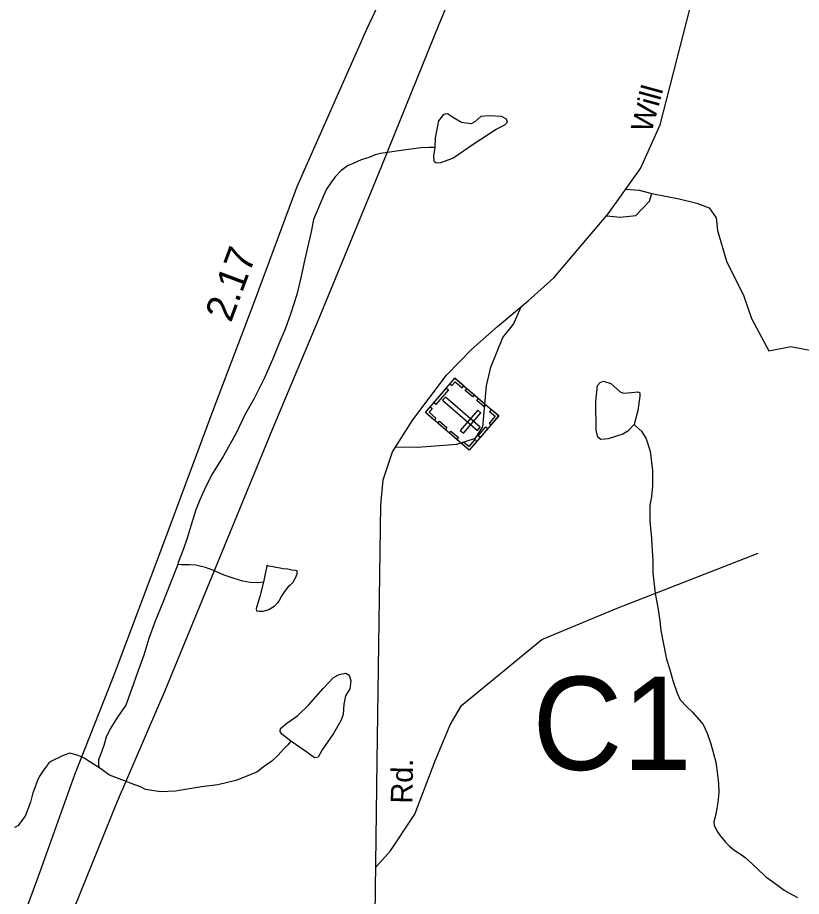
# Model space of a CAD drawing. Extents: x 2056842 to 2160602, y 826753 to 1016856.
# Drawn here: x 2070045 to 2073493, y 851288 to 855154 of the extents above; entities that cross this region are included whole.
import ezdxf

# ---------------------------------------------------------------- set-up
doc = ezdxf.new("R2010")
doc.units = 0
for name, color, linetype in [('Exist Cultural Cemetery CELL', 7, 'Continuous'), ('Exist Hydrographic Creek Single Shore', 7, 'Continuous'), ('Exist Hydrographic Misc Water Feature', 7, 'Continuous'), ('Exist Road Non-System Type 51', 7, 'Continuous'), ('Exist Road Primary Interstate Divided Center Attributed', 7, 'Continuous'), ('Exist Road Primary Interstate Mileage Hundredths English Label', 7, 'Continuous'), ('Exist Road Secondary Structure Culvert Number Label', 7, 'Continuous'), ('Exist Road Secondary Type 51 Attributed', 7, 'Continuous'), ('Exist Road Secondary Type 51 Label', 7, 'Continuous')]:
    doc.layers.add(name, color=color, linetype=linetype)

msp = doc.modelspace()

# ---------------------------------------------------------------- linework, layer by layer
at = {"layer": 'Exist Cultural Cemetery CELL'}
for points in [[(2072161.6, 853402), (2072031.9, 853251), (2071838.8, 853416.9), (2071968.5, 853567.9)], [(2071947, 853542.8), (2071955.7, 853535.3), (2071970, 853552), (2072000.7, 853525.7), (2072007.9, 853534.1), (2071968.6, 853568)], [(2071939.8, 853516.9), (2071884.5, 853452.5), (2071875.8, 853459.9), (2071931.1, 853524.3)], [(2072021.6, 853522.4), (2072054.4, 853494.2), (2072047, 853485.5), (2072014.2, 853513.8)], [(2072068.4, 853338.4), (2072080.5, 853352.6), (2071926.7, 853484.7), (2071914.5, 853470.6)], [(2072072.5, 853478.6), (2072105.4, 853450.3), (2072098, 853441.7), (2072065.1, 853469.9)], [(2071860.3, 853442.1), (2071869.1, 853434.6), (2071854.7, 853417.9), (2071885.4, 853391.6), (2071878.1, 853383.1), (2071838.8, 853416.9)], [(2072083.4, 853415.4), (2072069.2, 853427.6), (2071992.5, 853338.3), (2072006.7, 853326.1)], [(2072128.8, 853430.2), (2072121.4, 853421.6), (2072145.8, 853400.6), (2072119.4, 853369.9), (2072127.8, 853362.6), (2072161.6, 853402)], [(2071901, 853378.5), (2071933.8, 853350.2), (2071926.4, 853341.6), (2071893.6, 853369.8)], [(2072113.3, 853345.8), (2072079.6, 853306.5), (2072070.9, 853313.9), (2072104.7, 853353.3)], [(2071951, 853335.5), (2071983.8, 853307.3), (2071976.4, 853298.6), (2071943.5, 853326.8)], [(2071998.9, 853279.2), (2072006.3, 853287.8), (2072030.8, 853266.8), (2072057.2, 853297.6), (2072065.6, 853290.3), (2072031.8, 853251)]]:
    msp.add_lwpolyline(points, close=True, dxfattribs=at)
at = {"layer": 'Exist Hydrographic Creek Single Shore'}
for points in [[(2072757.3, 853363.7), (2072764.3, 853356.2), (2072789.3, 853334.2), (2072809.8, 853300.9), (2072827.7, 853247.2), (2072837.9, 853161.4), (2072837.9, 853094.9), (2072832.8, 853047.5), (2072826.4, 853008.3), (2072826.6, 852968.5), (2072826.6, 852940.5), (2072829.1, 852908.6), (2072832.8, 852862.5), (2072836.9, 852808.3), (2072838.9, 852766.7), (2072839.1, 852734.6), (2072839.3, 852710.6), (2072845.5, 852660.5), (2072849.4, 852620.6), (2072861.7, 852558.7), (2072869.9, 852500.7), (2072874, 852458.7), (2072887.5, 852390.4), (2072900, 852332.6), (2072912.1, 852290.5), (2072928.1, 852238.6), (2072946.1, 852182.7), (2072960.1, 852152.6), (2072988.4, 852122.8), (2073014.6, 852098.9), (2073042.5, 852065.1), (2073060.4, 852044.9), (2073078.6, 852006.8), (2073094.4, 851959), (2073106.7, 851917), (2073117, 851878.9), (2073124.5, 851823), (2073128.9, 851785), (2073129.1, 851745.2), (2073125.2, 851701.2), (2073121.1, 851675), (2073113.5, 851639.2), (2073107.3, 851617), (2073109.4, 851601.3), (2073121.5, 851577.2), (2073133.4, 851559.1), (2073159.4, 851527.2), (2073175.4, 851511.3), (2073197.1, 851491.4), (2073223.4, 851475.2), (2073245.3, 851459.3), (2073275.5, 851433.3), (2073305.8, 851403.5), (2073329.8, 851381.6), (2073335.5, 851375.5), (2073387.4, 851337.6), (2073417.8, 851315.6), (2073454.1, 851295.8), (2073475.8, 851283.6)], [(2071246.9, 851971.8), (2071232.7, 851953.6), (2071214.9, 851935.6), (2071190.9, 851909.6), (2071162.8, 851883.5), (2071124.9, 851857.6), (2071097, 851835.5), (2071005.6, 851798.2), (2070925, 851779), (2070853.4, 851770), (2070739.5, 851752.1), (2070673, 851748.2), (2070607.3, 851758.4), (2070585.2, 851770.6), (2070545, 851784.5), (2070515.1, 851796.3), (2070449.2, 851822.1), (2070407.2, 851852), (2070401.5, 851856.1)], [(2070401.5, 851856.1), (2070366.8, 851878), (2070337.1, 851895.9), (2070311, 851908), (2070275.3, 851917.8), (2070245.2, 851907.8), (2070191.1, 851881.6), (2070181.2, 851873.7), (2070167.1, 851855.6), (2070155.2, 851839.5), (2070141.2, 851817.7), (2070131.2, 851795.6), (2070121.1, 851765.5), (2070111.5, 851743.4), (2070101.8, 851703.4), (2070078.8, 851640.7), (2070045.9, 851599.2), (2070031.7, 851591.2)]]:
    msp.add_lwpolyline(points, dxfattribs=at)
at = {"layer": 'Exist Hydrographic Misc Water Feature'}
for points in [[(2071879.7, 854582.6), (2071874.8, 854546.4), (2071876, 854523.4), (2071886.3, 854515.7), (2071906.7, 854517), (2071959.2, 854536.2), (2072048.7, 854597.6), (2072149.8, 854662.9), (2072188.2, 854681.5), (2072199.7, 854694.3), (2072195.9, 854707.1), (2072174.1, 854718.6), (2072119.1, 854722.4), (2072083.3, 854718.6), (2072056.4, 854695.6), (2072039.8, 854686.6), (2071997.6, 854691.7), (2071963, 854713.5), (2071936.2, 854730.1), (2071918.3, 854727.6), (2071896.5, 854699.4), (2071881.2, 854625.2), (2071879.7, 854582.6)], [(2071879.7, 854582.6), (2071853.8, 854582.4), (2071819.8, 854580.3), (2071786, 854576.1), (2071742.1, 854570.2), (2071642, 854556.1), (2071618, 854550), (2071593.8, 854539.9), (2071556.1, 854527.8), (2071524.1, 854514), (2071496.2, 854502), (2071466.1, 854479.8), (2071442.3, 854453.8), (2071426.3, 854431.8), (2071404.4, 854399.8), (2071390.4, 854369.5), (2071374.4, 854331.8), (2071346.7, 854265.4), (2071336.9, 854211.7), (2071324.8, 854161.6), (2071308.8, 854091.4), (2071297.3, 854037.5), (2071289.1, 854003.5), (2071273.1, 853935.7), (2071247.5, 853853.5), (2071221.3, 853783.3), (2071193.8, 853719.3), (2071167.9, 853653.5), (2071130, 853567), (2071086.1, 853479.2), (2071043.9, 853407.2), (2071008, 853329.1), (2070986.5, 853289), (2070948.7, 853222.9), (2070902.8, 853148.7), (2070872.7, 853090.8), (2070846.8, 853032.6), (2070829, 852988.7), (2070809.1, 852922.7), (2070791.3, 852864.6), (2070775.3, 852816.7), (2070751.5, 852756.6), (2070749.4, 852748.8)], [(2072757.3, 853363.7), (2072729.2, 853335.5), (2072707.4, 853321.4), (2072643.5, 853300.9), (2072610.2, 853298.4), (2072597.4, 853308.6), (2072589.7, 853339.3), (2072588.5, 853467.3), (2072596.1, 853535.2), (2072607.6, 853549.3), (2072623, 853554.4), (2072655, 853544.1), (2072695.9, 853508.3), (2072710, 853501.9), (2072745.8, 853504.5), (2072772.7, 853508.3), (2072782.9, 853503.2), (2072782.9, 853489.1), (2072773.9, 853426.4), (2072757.3, 853363.7)], [(2070749.4, 852748.8), (2070715.6, 852662.6), (2070684, 852580.6), (2070650, 852498.5), (2070621.9, 852422.4), (2070600.1, 852350.2), (2070574.1, 852278.3), (2070546.4, 852198.5), (2070520.6, 852130.2), (2070484.9, 852076.3), (2070452.7, 852026.1), (2070434.9, 851988.2), (2070424.6, 851952), (2070410.9, 851915.9), (2070401, 851889.9), (2070401, 851882.2), (2070400.8, 851868), (2070401.5, 851856.1)], [(2071127.5, 852671.2), (2071099.7, 852667.3), (2071067.7, 852669.3), (2071035.5, 852675.4), (2070997.5, 852687.2), (2070953.5, 852701.1), (2070903.6, 852722.9), (2070871.6, 852734.7), (2070829.4, 852744.7), (2070801.3, 852746.6), (2070767.3, 852746.5), (2070749.4, 852748.8)], [(2071127.5, 852671.2), (2071135.1, 852707.3), (2071141.7, 852733.5), (2071143.3, 852745.4), (2071147.4, 852743.2), (2071169.4, 852739.4), (2071181.5, 852737.2), (2071199.5, 852733.3), (2071211.4, 852731.4), (2071233.3, 852729.7), (2071251.2, 852725.4), (2071267.6, 852723.7), (2071273.5, 852721.6), (2071273.3, 852705.4), (2071267.8, 852691.7), (2071255.5, 852669.6), (2071243.8, 852657.6), (2071235.6, 852649.5), (2071223.5, 852635.5), (2071215.9, 852625.3), (2071207.5, 852611.5), (2071195.4, 852589.4), (2071187.4, 852577.7), (2071173.7, 852563.5), (2071150.1, 852549.3), (2071123.6, 852541.5), (2071109.7, 852541.2), (2071097.6, 852543.4), (2071095.8, 852555.4), (2071101.7, 852575.2), (2071113.6, 852613.2), (2071127.5, 852671.2)], [(2071246.9, 851971.8), (2071207.6, 852001.7), (2071199.9, 852013.2), (2071201.2, 852027.3), (2071229.4, 852050.3), (2071278, 852084.9), (2071324, 852129.7), (2071389.3, 852202.7), (2071434, 852251.3), (2071459.6, 852264.1), (2071489.1, 852270.5), (2071503.1, 852261.5), (2071510.8, 852237.2), (2071505.7, 852201.4), (2071487.8, 852170.7), (2071480.1, 852133.5), (2071477.5, 852088.7), (2071468.6, 852063.1), (2071434, 852005.5), (2071385.4, 851932.6), (2071367.5, 851900.6), (2071350.9, 851898), (2071317.6, 851923.6), (2071246.9, 851971.8)]]:
    msp.add_lwpolyline(points, dxfattribs=at)
at = {"layer": 'Exist Road Non-System Type 51'}
for points in [[(2072720.2, 854399.5), (2072779.3, 854394.2), (2072835.4, 854379.6)], [(2072637.1, 854282.3), (2072696.3, 854275.7), (2072764.8, 854284), (2072825, 854346.3), (2072835.4, 854379.6)], [(2072835.4, 854379.6), (2072955.9, 854356.7), (2073032.7, 854338), (2073086.7, 854317.3), (2073117.9, 854273.6), (2073124.1, 854217.5), (2073163.6, 854082.4), (2073240.4, 853928.6), (2073273.7, 853830.9), (2073349.5, 853688.5), (2073447.1, 853707.2), (2073544.7, 853688.5), (2073671.4, 853649)], [(2071708.5, 853266.1), (2071804.2, 853264.5), (2071976.6, 853277), (2072059.7, 853304), (2072090.8, 853353.9), (2072107.4, 853534.7), (2072126.1, 853615.8), (2072180.1, 853746.7), (2072225.8, 853804.9), (2072259.8, 853881.3)], [(2071620.8, 851416.7), (2071684.8, 851488.5), (2071792.8, 851650.6), (2071882.1, 851885.5), (2071948.5, 852043.4), (2071997.3, 852127.6), (2072350.4, 852418.6), (2072682.8, 852555.8), (2073302.7, 852797.9)]]:
    msp.add_lwpolyline(points, dxfattribs=at)
at = {"layer": 'Exist Road Primary Interstate Divided Center Attributed'}
for points in [[(2074216.7, 860970.1), (2074021.5, 860500.2), (2073815.4, 859976.4), (2073622, 859511.9), (2073427.7, 859049.2), (2073236.9, 858626.2), (2073074.9, 858266.1), (2072932.8, 857987.1), (2072657.5, 857398.4), (2072403.7, 856861.9), (2072139.2, 856303.8), (2071877.4, 855733.1), (2071579.6, 855101.2), (2071273.6, 854409.9), (2071085.6, 853904), (2070902.9, 853421.6), (2070686.1, 852841.9), (2070467.5, 852262.2), (2070294.7, 851822.9), (2070133.7, 851371), (2069899.7, 850739.1), (2069637, 850017.2), (2069432.9, 849467.8)], [(2069680.8, 849743), (2069779.1, 849984.8), (2070052.7, 850634.7), (2070292, 851232.4), (2070483.7, 851707.7), (2070694.2, 852193.8), (2070934.4, 852778.9), (2071174.7, 853363.9), (2071371.7, 853832), (2071631.7, 854462.1), (2071899.9, 855124.6), (2072109.5, 855623.3), (2072403.7, 856334.4), (2072634.1, 856897.9), (2072835.6, 857393), (2073048, 857895.2), (2073172.1, 858176.1), (2073332.3, 858582.9), (2073503.2, 859015), (2073695.8, 859472.3), (2073907.2, 860005.2), (2074093.5, 860476.8), (2074268.9, 860894.5)]]:
    msp.add_lwpolyline(points, dxfattribs=at)
at = {"layer": 'Exist Road Secondary Type 51 Attributed'}
msp.add_lwpolyline([(2071613.2, 849416.2), (2071601.8, 849503.5), (2071603.9, 849877.6), (2071615.3, 850980.2), (2071626.7, 851883.2), (2071642.3, 853008.7), (2071652.7, 853120.9), (2071694.2, 853243.5), (2071783.5, 853384.9), (2071932, 853581.3), (2072042.1, 853693.5), (2072156.3, 853795.4), (2072291.3, 853907.6), (2072403.5, 854009.4), (2072643.4, 854291.1), (2072784.6, 854490.6), (2072871.8, 854681.8), (2073003.7, 855196.2)], dxfattribs=at)

# ---------------------------------------------------------------- texts
at = {"layer": 'Exist Road Primary Interstate Mileage Hundredths English Label'}
msp.add_text('2.17', height=125, rotation=69.6086, dxfattribs=at).set_placement((2070983.6, 853809))
at = {"layer": 'Exist Road Secondary Structure Culvert Number Label'}
msp.add_text('C1', height=410.1, dxfattribs=at).set_placement((2072309.7, 851844.8))
at = {"layer": 'Exist Road Secondary Type 51 Label'}
for s, rotation, p in [('Will', 74.7999, (2072832.7, 854642.4)), ('Rd.', 88.8155, (2071781.1, 851695.8))]:
    msp.add_text(s, height=95, rotation=rotation, dxfattribs=at).set_placement(p)

doc.saveas('drawing.dxf')
